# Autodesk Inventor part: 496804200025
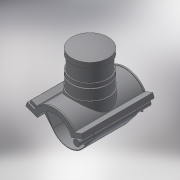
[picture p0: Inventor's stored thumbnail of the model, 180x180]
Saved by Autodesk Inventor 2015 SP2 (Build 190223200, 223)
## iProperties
Created: 2017-07
Part Number: 496804200025
Material: Generic
Description: PLASSON BALLOON SADDLE 200-2.1/2"
Document SubType Name: Modeling
Designer: KIM
Density: 1 g/cm^3
Appearance: Default
Author: KIM
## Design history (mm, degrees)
derived "496804.ipt"
feature "Solid1::496804.ipt"
feature "Solid2::496804.ipt"
tag "TaggingFeature1"
body "Solid1"
body "Solid2"
other parameters: "d4" = 176, "d5" = 0, "d40" = 119.6, "d96" = 234.6, "d97" = 3.52, "d98" = 0, "d120" = 100 deg, "d121" = 24.228, "d122" = 40 deg, "d124" = 138, "d126" = 0, "d143" = 206, "d145" = 23.07692, "d149" = 3, "d150" = 25.38462, "d153" = 176, "d154" = 0, "d159" = 6, "d161" = 3, "d162" = 105.6, "d163" = 0, "d168" = 104.54545, "d170" = 3, "d172" = 0, "d173" = 1, "d176" = 40 deg, "d177" = 16, "d180" = 0, "d185" = 57.2, "d186" = 57.2, "d187" = 115, "d188" = 9, "d190" = 0, "d191" = 184, "d193" = 6, "d194" = 4.4, "d195" = 90 deg, "d197" = 0, "d199" = 0, "d200" = 105, "d201" = 1, "d203" = 94.5, "d204" = 97.65, "d205" = 85.5, "d206" = 1.8, "d207" = 52.5, "d208" = 42, "d209" = 84, "d210" = 21, "d216" = 0, "d217" = 101, "d220" = 15.98, "d221" = 20 deg, "d223" = 12.51398, "d224" = 6.25699, "d226" = 0, "d227" = -17.6, "d228" = 3, "d229" = 44, "B_" = 202, "H_" = 105, "L_" = 176, "d_t" = 6, "d148" = 3, "d160" = 3, "d169" = 3, "d192" = 6, "d222" = 15.64248
